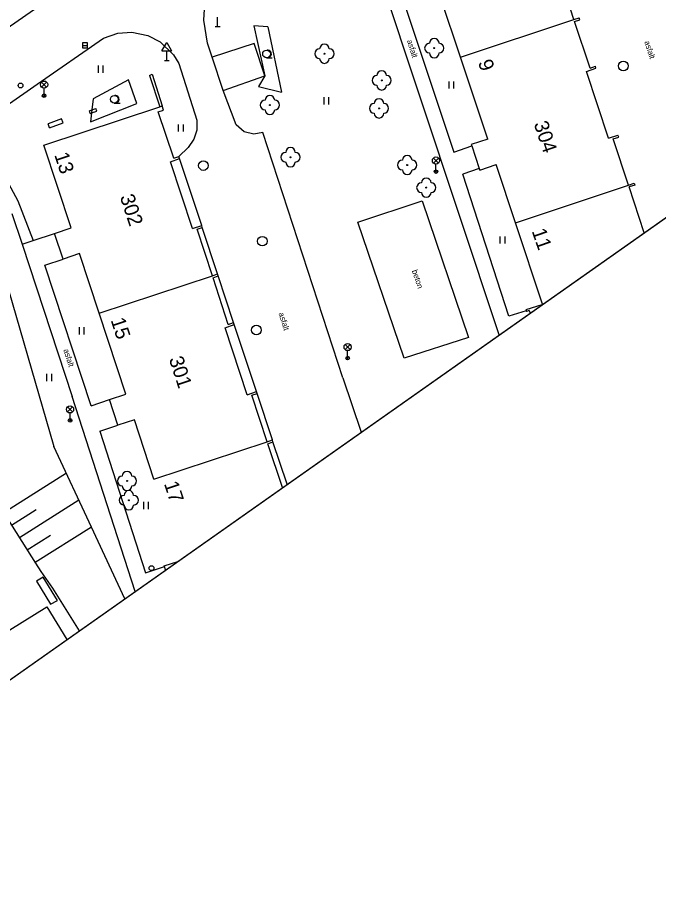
# Model space of a CAD drawing. Extents: x -492431 to -49218, y -1127123 to -112687.
# Drawn here: x -492309.7 to -492243, y -1127122.9 to -1127032.4 of the extents above; entities that cross this region are included whole.
import ezdxf

# ---------------------------------------------------------------- set-up
doc = ezdxf.new("R2010")
doc.units = 0
for name, color, linetype in [('Vrstva 1', 7, 'Continuous'), ('Vrstva 10', 7, 'Continuous'), ('Vrstva 11', 7, 'Continuous'), ('Vrstva 15', 7, 'Continuous'), ('Vrstva 21', 7, 'Continuous'), ('Vrstva 22', 7, 'Continuous'), ('Vrstva 24', 7, 'Continuous'), ('Vrstva 27', 7, 'Continuous'), ('Vrstva 31', 7, 'Continuous'), ('Vrstva 33', 7, 'Continuous'), ('Vrstva 34', 7, 'Continuous'), ('Vrstva 36', 7, 'Continuous'), ('Vrstva 40', 7, 'Continuous'), ('Vrstva 43', 7, 'Continuous'), ('Vrstva 44', 7, 'Continuous'), ('Vrstva 5', 7, 'Continuous'), ('Vrstva 60', 7, 'Continuous'), ('Vrstva 7', 7, 'Continuous')]:
    doc.layers.add(name, color=color, linetype=linetype)

msp = doc.modelspace()

# ---------------------------------------------------------------- linework, layer by layer
at = {"layer": 'Vrstva 1'}
msp.add_lwpolyline([(-492341.24, -1127122.91), (-492133.025, -1126976.26), (-492272.695, -1126862.455), (-492313.78, -1126867.2)], dxfattribs=at)
at = {"layer": 'Vrstva 10'}
for p, q in [((-492295.92, -1127038.44), (-492294.84, -1127041.7)), ((-492290.5, -1127054.04), (-492292.79, -1127047.07)), ((-492261.65, -1127048.11), (-492263.37, -1127048.69)), ((-492309.59, -1127051.48), (-492308.03, -1127055.6)), ((-492274.27, -1127053.69), (-492267.58, -1127051.46)), ((-492267.58, -1127051.46), (-492262.78, -1127065.67)), ((-492269.45, -1127067.82), (-492274.27, -1127053.69)), ((-492288.84, -1127059.07), (-492290.44, -1127054.24)), ((-492306.8, -1127058.14), (-492304.9, -1127057.52)), ((-492301.98, -1127072.75), (-492306.8, -1127058.14)), ((-492287.18, -1127064.11), (-492288.77, -1127059.27)), ((-492284.81, -1127071.28), (-492287.11, -1127064.31)), ((-492262.78, -1127065.67), (-492269.45, -1127067.82)), ((-492275.82, -1127069.87), (-492273.937, -1127075.507)), ((-492283.15, -1127076.31), (-492284.73, -1127071.48)), ((-492301.98, -1127072.75), (-492300.08, -1127072.12)), ((-492301.1, -1127075.41), (-492299.2, -1127074.78)), ((-492281.621, -1127080.919), (-492283.09, -1127076.52))]:
    msp.add_line(p, q, dxfattribs=at)
for points in [[(-492288.26, -1127040.02), (-492289.42, -1127036.56), (-492289.89, -1127035.11), (-492290.26, -1127032.72), (-492290.1, -1127029.83), (-492289.45, -1127028.22), (-492288.65, -1127026.91), (-492287.66, -1127025.7), (-492284.99, -1127023.84), (-492276.97, -1127018.26), (-492274.21, -1127016.34), (-492274.13, -1127016.28), (-492272.68, -1127015.29), (-492270.39, -1127013.71), (-492269.93, -1127013.4), (-492268.5, -1127012.44)], [(-492259.59, -1127065.402), (-492271.91, -1127028.26)], [(-492306.27, -1127030.45), (-492319.84, -1127039.87)], [(-492267.38, -1127030.76), (-492269.28, -1127031.47), (-492265.13, -1127043.91), (-492264.31, -1127046.41), (-492262.43, -1127045.76)], [(-492314.41, -1127044.09), (-492307.59, -1127039.35), (-492300.7, -1127034.57), (-492299.23, -1127034.07), (-492297.76, -1127033.96), (-492296.09, -1127034.31), (-492294.81, -1127034.95), (-492293.43, -1127036.32), (-492292.89, -1127037.2), (-492291.02, -1127043.09), (-492291, -1127044.12), (-492291.3, -1127045.08), (-492291.89, -1127045.92), (-492292.86, -1127046.86)], [(-492288.26, -1127040.02), (-492283.92, -1127038.48), (-492285.06, -1127035.14), (-492289.42, -1127036.56)], [(-492295.92, -1127038.44), (-492295.64, -1127038.33), (-492294.6, -1127041.62)], [(-492275.82, -1127069.87), (-492284.16, -1127044.38), (-492285.09, -1127044.53), (-492286.07, -1127044.29), (-492286.9, -1127043.58), (-492288.26, -1127040.02)], [(-492314.41, -1127044.09), (-492311.78, -1127047.5), (-492309.59, -1127051.48)], [(-492256.76, -1127062.91), (-492258.57, -1127063.45), (-492263.37, -1127048.69)], [(-492310.23, -1127052.78), (-492309.17, -1127055.98)], [(-492308.03, -1127055.6), (-492305.78, -1127054.86)], [(-492309.17, -1127055.98), (-492303.95, -1127071.78)], [(-492297.407, -1127092.037), (-492303.95, -1127071.78)], [(-492301.1, -1127075.41), (-492296.33, -1127090.12), (-492294.37, -1127089.46)]]:
    msp.add_lwpolyline(points, dxfattribs=at)
at = {"layer": 'Vrstva 11'}
for points in [[(-492309.17, -1127055.98), (-492308.03, -1127055.6)], [(-492318.08, -1127072.8), (-492307.77, -1127089.11)], [(-492307.77, -1127089.11), (-492307.2, -1127089.99)]]:
    msp.add_lwpolyline(points, dxfattribs=at)
at = {"layer": 'Vrstva 15'}
for p, q in [((-492304.55, -1127079.77), (-492311.07, -1127083.89)), ((-492303.26, -1127082.56), (-492309.44, -1127086.47)), ((-492307.71, -1127083.57), (-492310.25, -1127085.18)), ((-492301.96, -1127085.36), (-492307.8, -1127089.05)), ((-492306.22, -1127086.24), (-492308.62, -1127087.76))]:
    msp.add_line(p, q, dxfattribs=at)
at = {"layer": 'Vrstva 21'}
for p, q in [((-492283.63, -1127033.4), (-492285.08, -1127033.31)), ((-492283.63, -1127033.4), (-492282.21, -1127040.18)), ((-492284.59, -1127039.59), (-492282.21, -1127040.18)), ((-492302.05, -1127043.25), (-492297.25, -1127041.35)), ((-492312.84, -1127052.97), (-492305.85, -1127076.98))]:
    msp.add_line(p, q, dxfattribs=at)
for points in [[(-492285.08, -1127033.31), (-492283.92, -1127038.48), (-492284.59, -1127039.59)], [(-492297.25, -1127041.35), (-492298.1, -1127038.9), (-492301.77, -1127040.87), (-492301.91, -1127042.02), (-492301.94, -1127042.34), (-492302.05, -1127043.25)], [(-492298.489, -1127092.799), (-492301.96, -1127085.36), (-492305.85, -1127076.98)]]:
    msp.add_lwpolyline(points, dxfattribs=at)
at = {"layer": 'Vrstva 22'}
for centre in [(-492266.33, -1127035.61), (-492277.74, -1127036.19), (-492271.79, -1127038.96), (-492283.41, -1127041.52), (-492272.07, -1127041.87), (-492281.27, -1127046.94), (-492269.14, -1127047.75), (-492267.16, -1127050.1), (-492298.26, -1127080.57), (-492298.07, -1127082.57)]:
    msp.add_circle(centre, 0.05, dxfattribs=at)
for centre, start, end in [((-492266.33, -1127035.11), 360, 180), ((-492278.24, -1127036.19), 90, 270), ((-492277.74, -1127035.69), 360, 180), ((-492277.24, -1127036.19), 270, 90), ((-492266.83, -1127035.61), 90, 270), ((-492265.83, -1127035.61), 270, 90), ((-492266.33, -1127036.11), 180, 0), ((-492277.74, -1127036.69), 180, 0), ((-492272.29, -1127038.96), 90, 270), ((-492271.79, -1127038.46), 360, 180), ((-492271.29, -1127038.96), 270, 90), ((-492271.79, -1127039.46), 180, 0), ((-492283.91, -1127041.52), 90, 270), ((-492283.41, -1127041.02), 360, 180), ((-492282.91, -1127041.52), 270, 90), ((-492272.07, -1127041.37), 360, 180), ((-492283.41, -1127042.02), 180, 0), ((-492272.57, -1127041.87), 90, 270), ((-492271.57, -1127041.87), 270, 90), ((-492272.07, -1127042.37), 180, 0), ((-492281.77, -1127046.94), 90, 270), ((-492281.27, -1127046.44), 360, 180), ((-492280.77, -1127046.94), 270, 90), ((-492281.27, -1127047.44), 180, 0), ((-492269.64, -1127047.75), 90, 270), ((-492269.14, -1127047.25), 360, 180), ((-492268.64, -1127047.75), 270, 90), ((-492269.14, -1127048.25), 180, 0), ((-492267.16, -1127049.6), 360, 180), ((-492267.66, -1127050.1), 90, 270), ((-492266.66, -1127050.1), 270, 90), ((-492267.16, -1127050.6), 180, 0), ((-492298.76, -1127080.57), 90, 270), ((-492298.26, -1127080.07), 360, 180), ((-492297.76, -1127080.57), 270, 90), ((-492298.26, -1127081.07), 180, 0), ((-492298.07, -1127082.07), 360, 180), ((-492298.57, -1127082.57), 90, 270), ((-492297.57, -1127082.57), 270, 90), ((-492298.07, -1127083.07), 180, 0)]:
    msp.add_arc(centre, 0.5, start, end, dxfattribs=at)
at = {"layer": 'Vrstva 24'}
for p, q in [((-492301.41, -1127042.16), (-492301.5, -1127041.88)), ((-492306.3, -1127043.9), (-492306.46, -1127043.46)), ((-492306.3, -1127043.9), (-492304.9, -1127043.37))]:
    msp.add_line(p, q, dxfattribs=at)
for points in [[(-492302.09, -1127042.39), (-492302.17, -1127042.11), (-492301.91, -1127042.02), (-492301.5, -1127041.88)], [(-492304.9, -1127043.37), (-492305.08, -1127042.94), (-492306.46, -1127043.46)], [(-492302.09, -1127042.39), (-492301.94, -1127042.34), (-492301.41, -1127042.16)], [(-492306.96, -1127090.56), (-492307.65, -1127090.98), (-492306.21, -1127093.38), (-492305.5, -1127092.99), (-492306.96, -1127090.56)]]:
    msp.add_lwpolyline(points, dxfattribs=at)
at = {"layer": 'Vrstva 27'}
msp.add_line((-492302.88, -1127035.32), (-492302.38, -1127035.32), dxfattribs=at)
msp.add_lwpolyline([(-492302.88, -1127035.57), (-492302.38, -1127035.57), (-492302.38, -1127035.07), (-492302.88, -1127035.07)], close=True, dxfattribs=at)
for centre in [(-492246.68, -1127037.46), (-492290.32, -1127047.81), (-492284.19, -1127055.66), (-492284.81, -1127064.89)]:
    msp.add_circle(centre, 0.5, dxfattribs=at)
at = {"layer": 'Vrstva 31'}
for centre in [(-492309.32, -1127039.49), (-492295.72, -1127089.63)]:
    msp.add_circle(centre, 0.25, dxfattribs=at)
at = {"layer": 'Vrstva 33'}
for p, q in [((-492307.145, -1127039.135), (-492306.615, -1127039.665)), ((-492307.145, -1127039.665), (-492306.615, -1127039.135)), ((-492306.88, -1127040.55), (-492306.88, -1127039.775)), ((-492266.415, -1127047.025), (-492265.885, -1127047.555)), ((-492266.415, -1127047.555), (-492265.885, -1127047.025)), ((-492266.15, -1127048.44), (-492266.15, -1127047.665)), ((-492275.595, -1127066.395), (-492275.065, -1127066.925)), ((-492275.595, -1127066.925), (-492275.065, -1127066.395)), ((-492275.33, -1127067.81), (-492275.33, -1127067.035)), ((-492304.445, -1127072.865), (-492303.915, -1127073.395)), ((-492304.445, -1127073.395), (-492303.915, -1127072.865)), ((-492304.18, -1127074.28), (-492304.18, -1127073.505))]:
    msp.add_line(p, q, dxfattribs=at)
for centre, radius in [((-492306.88, -1127039.4), 0.375), ((-492306.88, -1127040.55), 0.19), ((-492306.88, -1127040.55), 0.05), ((-492266.15, -1127047.29), 0.375), ((-492266.15, -1127048.44), 0.19), ((-492266.15, -1127048.44), 0.05), ((-492275.33, -1127066.66), 0.375), ((-492275.33, -1127067.81), 0.19), ((-492275.33, -1127067.81), 0.05), ((-492304.18, -1127073.13), 0.375), ((-492304.18, -1127074.28), 0.19), ((-492304.18, -1127074.28), 0.05)]:
    msp.add_circle(centre, radius, dxfattribs=at)
at = {"layer": 'Vrstva 34'}
for p, q in [((-492288.84, -1127033.38), (-492288.84, -1127032.38)), ((-492289.09, -1127033.38), (-492288.59, -1127033.38)), ((-492294.63, -1127035.88), (-492294.13, -1127035.03)), ((-492294.13, -1127035.03), (-492293.63, -1127035.88)), ((-492294.63, -1127035.88), (-492293.63, -1127035.88)), ((-492294.13, -1127036.88), (-492294.13, -1127035.88)), ((-492294.38, -1127036.88), (-492293.88, -1127036.88))]:
    msp.add_line(p, q, dxfattribs=at)
at = {"layer": 'Vrstva 36'}
for p, q in [((-492283.76, -1127036.61), (-492283.66, -1127036.61)), ((-492283.66, -1127036.61), (-492283.16, -1127036.61)), ((-492301.24, -1127038.16), (-492301.24, -1127037.41)), ((-492300.74, -1127038.16), (-492300.74, -1127037.41)), ((-492264.79, -1127039.81), (-492264.79, -1127039.06)), ((-492264.29, -1127039.81), (-492264.29, -1127039.06)), ((-492277.78, -1127041.46), (-492277.78, -1127040.71)), ((-492277.28, -1127041.46), (-492277.28, -1127040.71)), ((-492299.58, -1127041.32), (-492299.48, -1127041.32)), ((-492299.48, -1127041.32), (-492298.98, -1127041.32)), ((-492292.9, -1127044.28), (-492292.9, -1127043.53)), ((-492292.4, -1127044.28), (-492292.4, -1127043.53)), ((-492259.47, -1127055.91), (-492259.47, -1127055.16)), ((-492258.97, -1127055.91), (-492258.97, -1127055.16)), ((-492303.2, -1127065.36), (-492303.2, -1127064.61)), ((-492302.7, -1127065.36), (-492302.7, -1127064.61)), ((-492306.59, -1127070.19), (-492306.59, -1127069.44)), ((-492306.09, -1127070.19), (-492306.09, -1127069.44)), ((-492296.51, -1127083.5), (-492296.51, -1127082.75)), ((-492296.01, -1127083.5), (-492296.01, -1127082.75))]:
    msp.add_line(p, q, dxfattribs=at)
for centre in [(-492283.76, -1127036.21), (-492299.58, -1127040.92)]:
    msp.add_circle(centre, 0.4, dxfattribs=at)
for centre in [(-492283.66, -1127036.21), (-492299.48, -1127040.92)]:
    msp.add_arc(centre, 0.4, 259.69515, 97.18076, dxfattribs=at)
at = {"layer": 'Vrstva 5'}
for p, q in [((-492251.81, -1127032.64), (-492253.39, -1127027.81)), ((-492263.6, -1127036.56), (-492251.81, -1127032.64)), ((-492251.81, -1127032.64), (-492251.26, -1127032.46)), ((-492251.74, -1127032.84), (-492251.19, -1127032.66)), ((-492250.12, -1127037.68), (-492251.74, -1127032.84)), ((-492251.19, -1127032.66), (-492251.26, -1127032.46)), ((-492250.12, -1127037.68), (-492249.57, -1127037.5)), ((-492249.52, -1127037.7), (-492249.57, -1127037.5)), ((-492250.49, -1127038.02), (-492249.52, -1127037.7)), ((-492248.21, -1127044.97), (-492250.49, -1127038.02)), ((-492295.01, -1127042.24), (-492294.46, -1127042.04)), ((-492294.46, -1127042.04), (-492294.6, -1127041.62)), ((-492293.41, -1127047.04), (-492295.01, -1127042.24)), ((-492248.21, -1127044.97), (-492247.24, -1127044.65)), ((-492247.16, -1127044.85), (-492247.24, -1127044.65)), ((-492304.08, -1127054.29), (-492306.92, -1127045.7)), ((-492260.77, -1127045.06), (-492262.48, -1127045.62)), ((-492247.72, -1127045.04), (-492247.16, -1127044.85)), ((-492246.13, -1127049.84), (-492247.72, -1127045.04)), ((-492293.75, -1127047.42), (-492292.79, -1127047.07)), ((-492291.47, -1127054.36), (-492293.75, -1127047.42)), ((-492293.41, -1127047.04), (-492292.86, -1127046.86)), ((-492292.79, -1127047.07), (-492292.86, -1127046.86)), ((-492261.6, -1127048.28), (-492259.89, -1127047.71)), ((-492257.88, -1127053.75), (-492246.13, -1127049.84)), ((-492246.13, -1127049.84), (-492245.56, -1127049.65)), ((-492245.5, -1127049.84), (-492246.07, -1127050.03)), ((-492244.512, -1127054.783), (-492246.07, -1127050.03)), ((-492245.56, -1127049.65), (-492245.5, -1127049.84)), ((-492305.78, -1127054.86), (-492304.08, -1127054.29)), ((-492291.47, -1127054.36), (-492290.5, -1127054.04)), ((-492290.98, -1127054.43), (-492290.44, -1127054.24)), ((-492289.38, -1127059.26), (-492290.98, -1127054.43)), ((-492290.44, -1127054.24), (-492290.5, -1127054.04)), ((-492304.9, -1127057.52), (-492305.78, -1127054.86)), ((-492303.2, -1127056.95), (-492304.9, -1127057.52)), ((-492301.15, -1127063.15), (-492289.38, -1127059.26)), ((-492289.38, -1127059.26), (-492288.84, -1127059.07)), ((-492289.32, -1127059.46), (-492288.77, -1127059.27)), ((-492288.77, -1127059.27), (-492288.84, -1127059.07)), ((-492287.73, -1127064.3), (-492289.32, -1127059.46)), ((-492256.79, -1127062.76), (-492255.106, -1127062.244)), ((-492256.47, -1127062.87), (-492256.74, -1127062.97)), ((-492256.47, -1127062.87), (-492256.378, -1127063.14)), ((-492288.06, -1127064.65), (-492287.11, -1127064.31)), ((-492285.76, -1127071.62), (-492288.06, -1127064.65)), ((-492287.73, -1127064.3), (-492287.18, -1127064.11)), ((-492287.11, -1127064.31), (-492287.18, -1127064.11)), ((-492300.08, -1127072.12), (-492298.37, -1127071.56)), ((-492285.76, -1127071.62), (-492284.81, -1127071.28)), ((-492285.28, -1127071.67), (-492284.73, -1127071.48)), ((-492283.7, -1127076.5), (-492285.28, -1127071.67)), ((-492284.73, -1127071.48), (-492284.81, -1127071.28)), ((-492299.2, -1127074.78), (-492300.08, -1127072.12)), ((-492297.49, -1127074.22), (-492299.2, -1127074.78)), ((-492283.7, -1127076.5), (-492283.15, -1127076.31)), ((-492283.09, -1127076.52), (-492283.15, -1127076.31)), ((-492295.46, -1127080.38), (-492283.7, -1127076.5)), ((-492283.61, -1127076.7), (-492283.09, -1127076.52)), ((-492282.09, -1127081.25), (-492283.61, -1127076.7)), ((-492312.41, -1127097.25), (-492306.59, -1127093.66)), ((-492306.59, -1127093.66), (-492304.503, -1127097.035))]:
    msp.add_line(p, q, dxfattribs=at)
for points in [[(-492263.6, -1127036.56), (-492265.64, -1127030.41)], [(-492260.77, -1127045.06), (-492263.6, -1127036.56)], [(-492306.92, -1127045.7), (-492294.84, -1127041.7), (-492294.6, -1127041.62)], [(-492262.48, -1127045.62), (-492262.43, -1127045.76), (-492261.65, -1127048.11), (-492261.6, -1127048.28)], [(-492257.88, -1127053.75), (-492259.89, -1127047.71)], [(-492255.065, -1127062.215), (-492257.88, -1127053.75)], [(-492301.15, -1127063.15), (-492303.2, -1127056.95)], [(-492256.79, -1127062.76), (-492256.76, -1127062.91), (-492256.74, -1127062.97)], [(-492298.37, -1127071.56), (-492301.15, -1127063.15)], [(-492295.46, -1127080.38), (-492297.49, -1127074.22)], [(-492294.25, -1127089.814), (-492294.37, -1127089.46), (-492294.39, -1127089.39), (-492292.981, -1127088.92)]]:
    msp.add_lwpolyline(points, dxfattribs=at)
at = {"layer": 'Vrstva 60'}
msp.add_lwpolyline([(-492431.031, -1127000), (-492431.031, -1127013.124), (-492341.24, -1127122.91), (-492166.731, -1127000)], dxfattribs=at)
at = {"layer": 'Vrstva 7'}
msp.add_lwpolyline([(-492307.2, -1127089.99), (-492306.01, -1127091.71), (-492303.219, -1127096.131)], dxfattribs=at)

# ---------------------------------------------------------------- texts
at = {"layer": 'Vrstva 40'}
for s, rotation, p in [('asfalt', 287.5742, (-492269.18, -1127034.841)), ('asfalt', 288.05591, (-492244.509, -1127034.956)), ('beton', 288.80559, (-492268.663, -1127058.743)), ('asfalt', 287.5742, (-492282.52, -1127063.171)), ('asfalt', 287.5742, (-492304.88, -1127066.951))]:
    msp.add_text(s, height=0.6, rotation=rotation, dxfattribs=at).set_placement(p)
at = {"layer": 'Vrstva 43'}
for s, rotation, p in [('304', 288.43495, (-492256.004, -1127043.459)), ('302', 288.25495, (-492299.017, -1127051.049)), ('301', 288.27377, (-492293.926, -1127067.889))]:
    msp.add_text(s, height=1.5, rotation=rotation, dxfattribs=at).set_placement(p)
at = {"layer": 'Vrstva 44'}
for s, rotation, p in [('9', 288.43495, (-492261.799, -1127037.065)), ('13', 288.25495, (-492305.832, -1127046.686)), ('11', 289.2392, (-492256.216, -1127054.609)), ('15', 288.27377, (-492299.973, -1127063.866)), ('17', 288.29716, (-492294.435, -1127080.85))]:
    msp.add_text(s, height=1.5, rotation=rotation, dxfattribs=at).set_placement(p)

doc.saveas('drawing.dxf')
